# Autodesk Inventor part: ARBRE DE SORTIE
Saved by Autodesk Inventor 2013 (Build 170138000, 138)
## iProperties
Created: 2012-12
Part Number: ARBRE DE SORTIE
Material: Générique
Document SubType Name: Modeling
Designer: jost thierry
Density: 1 g/cm^3
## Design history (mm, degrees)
node "ARBRE DE SORTIE1"
node "ARBRE DE SORTIE"
node "Base1"
